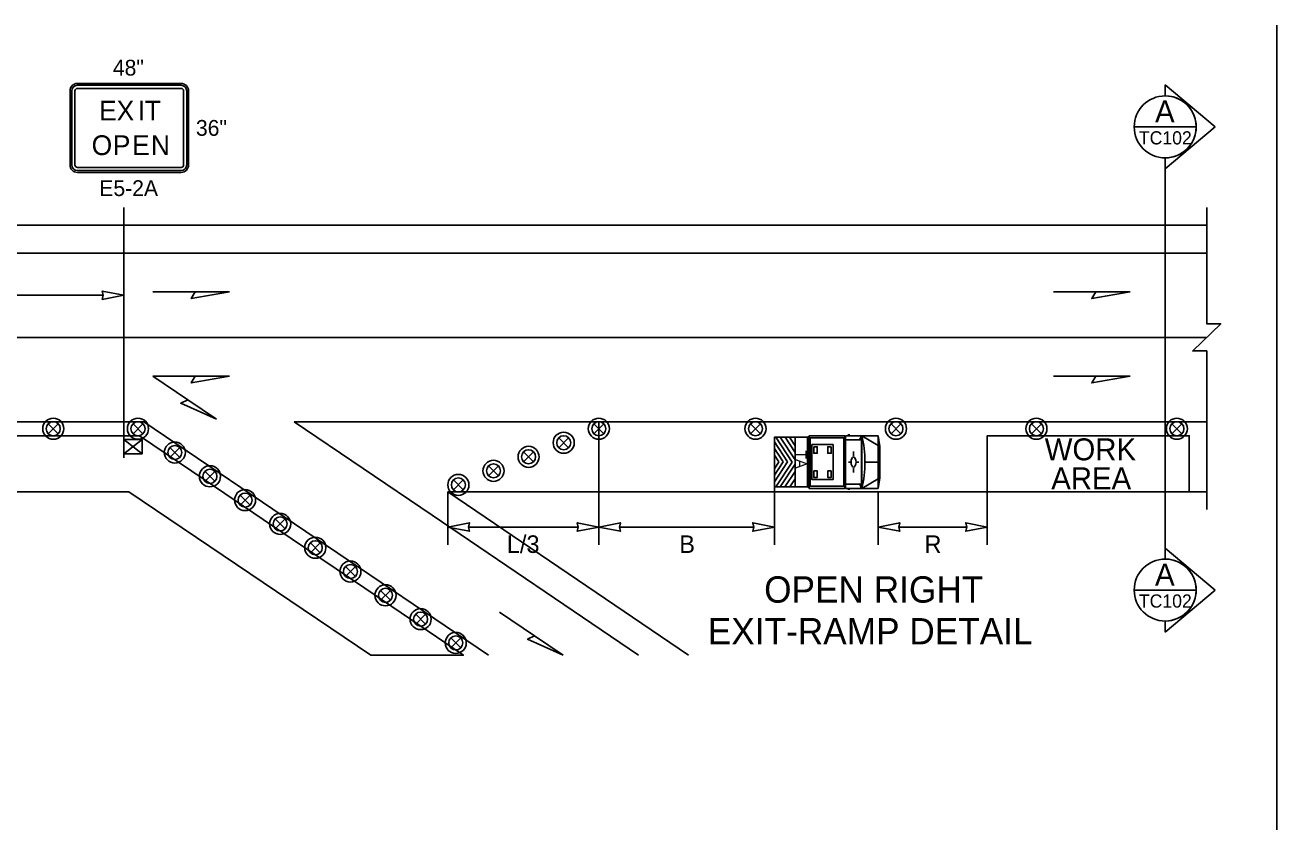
# Model space of a CAD drawing. Extents: x 99999.1 to 100055.7, y 99995 to 100013.2.
# Drawn here: x 100022.17 to 100027.88, y 100005.29 to 100008.92 of the extents above; entities that cross this region are included whole.
import ezdxf

# ---------------------------------------------------------------- set-up
doc = ezdxf.new("R2010")
doc.units = 0
for name, color, linetype in [('RD_MK_LineEdgeYellow', 7, 'Continuous'), ('RD_MK_LineLane', 7, 'Continuous'), ('SH_DE_DetailHeading2Text', 7, 'Continuous'), ('SH_TI_WZSectionCut', 7, 'Continuous'), ('TR_SN_ConstructionSigns', 7, 'Continuous'), ('TR_WZ_PortableSignMount5ftMinBlk-Org', 7, 'Continuous'), ('TR_WZ_TrafficSafetyDrum', 7, 'Continuous'), ('TR_WZ_TransportableAttenuator', 7, 'Continuous'), ('TR_WZ_WorkAreaLabel', 7, 'Continuous'), ('TR_WZ_WorkZoneDetails', 7, 'Continuous'), ('TR_WZ_WorkZoneTextCurrent', 7, 'Continuous')]:
    doc.layers.add(name, color=color, linetype=linetype)

msp = doc.modelspace()

# ---------------------------------------------------------------- linework, layer by layer
at = {"layer": 'RD_MK_LineEdgeYellow'}
for p, q in [((100020.32, 100007.8789), (100027.555, 100007.8789)), ((100020.32, 100007.1109), (100022.7119, 100007.1109)), ((100024.2815, 100006.047), (100022.7119, 100007.1109)), ((100024.0968, 100007.1109), (100027.555, 100007.1109)), ((100024.9659, 100006.047), (100024.0249, 100006.6849))]:
    msp.add_line(p, q, dxfattribs=at)
at = {"layer": 'RD_MK_LineLane'}
msp.add_lwpolyline([(100027.555, 100007.4949), (100020.32, 100007.4949)], dxfattribs=at)
at = {"layer": 'SH_TI_WZSectionCut'}
for p, q in [((100027.3657, 100008.5953), (100027.3657, 100008.6452)), ((100027.3657, 100008.6452), (100027.5938, 100008.454)), ((100027.5938, 100008.454), (100027.3657, 100008.2629)), ((100027.3657, 100008.2629), (100027.3657, 100008.3128)), ((100027.3657, 100008.2629), (100027.3657, 100006.5349)), ((100027.3657, 100006.5349), (100027.3657, 100006.485)), ((100027.5939, 100006.3438), (100027.3657, 100006.5349)), ((100027.3657, 100006.1526), (100027.5939, 100006.3438)), ((100027.3657, 100006.2025), (100027.3657, 100006.1526))]:
    msp.add_line(p, q, dxfattribs=at)
for points in [[(100027.2245, 100008.4541), (100027.5069, 100008.4541)], [(100027.2245, 100006.3438), (100027.5069, 100006.3438)]]:
    msp.add_lwpolyline(points, dxfattribs=at)
for centre in [(100027.3657, 100008.454), (100027.3657, 100006.3438)]:
    msp.add_circle(centre, 0.1412, dxfattribs=at)
for centre in [(100027.3657, 100008.454), (100027.3657, 100006.3438)]:
    msp.add_arc(centre, 0.1412, 269.9978, 90.0022, dxfattribs=at)
at = {"layer": 'TR_SN_ConstructionSigns'}
for p, q in [((100022.3752, 100008.6182), (100022.3752, 100008.2807)), ((100022.3837, 100008.6182), (100022.3837, 100008.2807)), ((100022.3977, 100008.2807), (100022.3977, 100008.6182)), ((100022.8815, 100008.6519), (100022.409, 100008.6519)), ((100022.8815, 100008.6435), (100022.409, 100008.6435)), ((100022.409, 100008.6294), (100022.8815, 100008.6294)), ((100022.8927, 100008.6182), (100022.8927, 100008.2807)), ((100022.9068, 100008.2807), (100022.9068, 100008.6182)), ((100022.9152, 100008.2807), (100022.9152, 100008.6182)), ((100022.8815, 100008.2694), (100022.409, 100008.2694)), ((100022.409, 100008.2553), (100022.8815, 100008.2553)), ((100022.409, 100008.2469), (100022.8815, 100008.2469))]:
    msp.add_line(p, q, dxfattribs=at)
for centre, radius, start, end in [((100022.409, 100008.6182), 0.0338, 90, 180), ((100022.409, 100008.6182), 0.0253, 90, 180), ((100022.409, 100008.6182), 0.0112, 90, 180), ((100022.8815, 100008.6182), 0.0338, 360, 90), ((100022.8815, 100008.6182), 0.0253, 360, 90), ((100022.8815, 100008.6182), 0.0112, 360, 90), ((100022.409, 100008.2807), 0.0338, 180, 270), ((100022.409, 100008.2807), 0.0253, 180, 270), ((100022.409, 100008.2807), 0.0112, 180, 270), ((100022.8815, 100008.2807), 0.0338, 270, 0), ((100022.8815, 100008.2807), 0.0253, 270, 0), ((100022.8815, 100008.2807), 0.0112, 270, 0)]:
    msp.add_arc(centre, radius, start, end, dxfattribs=at)
at = {"layer": 'TR_WZ_PortableSignMount5ftMinBlk-Org'}
for p, q in [((100022.6202, 100007.0469), (100022.6202, 100006.9469)), ((100022.7036, 100006.9644), (100022.6202, 100007.0294)), ((100022.7036, 100007.0294), (100022.6202, 100006.9644)), ((100022.6619, 100006.9969), (100022.6619, 100006.9969)), ((100022.6621, 100006.9968), (100022.6621, 100006.9968))]:
    msp.add_line(p, q, dxfattribs=at)
for points in [[(100022.7036, 100006.9644), (100022.7036, 100007.0294), (100022.6202, 100007.0294), (100022.6202, 100006.9644)], [(100022.6202, 100007.0294), (100022.7036, 100007.0294), (100022.7036, 100006.9644), (100022.6202, 100006.9644)]]:
    msp.add_lwpolyline(points, close=True, dxfattribs=at)
at = {"layer": 'TR_WZ_TrafficSafetyDrum'}
for p, q in [((100022.2763, 100007.1015), (100022.3215, 100007.0563)), ((100022.3215, 100007.1015), (100022.2763, 100007.0563)), ((100022.6622, 100007.1015), (100022.7075, 100007.0563)), ((100022.7075, 100007.1015), (100022.6622, 100007.0563)), ((100024.7622, 100007.1015), (100024.8074, 100007.0563)), ((100024.8074, 100007.1015), (100024.7622, 100007.0563)), ((100025.4763, 100007.1015), (100025.5215, 100007.0563)), ((100025.5215, 100007.1015), (100025.4763, 100007.0563)), ((100026.1163, 100007.1015), (100026.1615, 100007.0563)), ((100026.1615, 100007.1015), (100026.1163, 100007.0563)), ((100026.7563, 100007.1015), (100026.8015, 100007.0563)), ((100026.8015, 100007.1015), (100026.7563, 100007.0563)), ((100027.3963, 100007.1015), (100027.4415, 100007.0563)), ((100027.4415, 100007.1015), (100027.3963, 100007.0563)), ((100024.6022, 100007.0375), (100024.6474, 100006.9923)), ((100024.6474, 100007.0375), (100024.6022, 100006.9923)), ((100022.8303, 100006.9931), (100022.8755, 100006.9478)), ((100022.8755, 100006.9931), (100022.8303, 100006.9478)), ((100024.4422, 100006.9735), (100024.4874, 100006.9283)), ((100024.4874, 100006.9735), (100024.4422, 100006.9283)), ((100024.2822, 100006.9095), (100024.3274, 100006.8643)), ((100024.3274, 100006.9095), (100024.2822, 100006.8643)), ((100022.9903, 100006.8846), (100023.0355, 100006.8394)), ((100023.0355, 100006.8846), (100022.9903, 100006.8394)), ((100024.1221, 100006.8455), (100024.1674, 100006.8003)), ((100024.1674, 100006.8455), (100024.1221, 100006.8003)), ((100023.1503, 100006.7762), (100023.1955, 100006.7309)), ((100023.1955, 100006.7762), (100023.1503, 100006.7309)), ((100023.3103, 100006.6677), (100023.3555, 100006.6225)), ((100023.3555, 100006.6677), (100023.3103, 100006.6225)), ((100023.4703, 100006.5593), (100023.5155, 100006.514)), ((100023.5155, 100006.5593), (100023.4703, 100006.514)), ((100023.6303, 100006.4508), (100023.6755, 100006.4056)), ((100023.6755, 100006.4508), (100023.6303, 100006.4056)), ((100023.7903, 100006.3424), (100023.8355, 100006.2971)), ((100023.8355, 100006.3424), (100023.7903, 100006.2971)), ((100023.9503, 100006.2339), (100023.9955, 100006.1887)), ((100023.9955, 100006.2339), (100023.9503, 100006.1887)), ((100024.1103, 100006.1255), (100024.1555, 100006.0802)), ((100024.1555, 100006.1255), (100024.1103, 100006.0802))]:
    msp.add_line(p, q, dxfattribs=at)
for centre, radius in [((100022.2989, 100007.0789), 0.048), ((100022.2989, 100007.0789), 0.048), ((100022.6849, 100007.0789), 0.048), ((100022.6849, 100007.0789), 0.048), ((100024.7848, 100007.0789), 0.048), ((100024.7848, 100007.0789), 0.048), ((100025.4989, 100007.0789), 0.048), ((100025.4989, 100007.0789), 0.048), ((100026.1389, 100007.0789), 0.048), ((100026.1389, 100007.0789), 0.048), ((100026.7789, 100007.0789), 0.048), ((100026.7789, 100007.0789), 0.048), ((100027.4189, 100007.0789), 0.048), ((100027.4189, 100007.0789), 0.048), ((100022.2989, 100007.0789), 0.032), ((100022.6849, 100007.0789), 0.032), ((100024.7848, 100007.0789), 0.032), ((100025.4989, 100007.0789), 0.032), ((100026.1389, 100007.0789), 0.032), ((100026.7789, 100007.0789), 0.032), ((100027.4189, 100007.0789), 0.032), ((100022.8529, 100006.9705), 0.048), ((100022.8529, 100006.9705), 0.048), ((100024.6248, 100007.0149), 0.048), ((100024.6248, 100007.0149), 0.048), ((100024.6248, 100007.0149), 0.032), ((100022.8529, 100006.9705), 0.032), ((100024.4648, 100006.9509), 0.048), ((100024.4648, 100006.9509), 0.048), ((100024.4648, 100006.9509), 0.032), ((100023.0129, 100006.862), 0.048), ((100023.0129, 100006.862), 0.048), ((100023.0129, 100006.862), 0.032), ((100024.3048, 100006.8869), 0.048), ((100024.3048, 100006.8869), 0.048), ((100024.3048, 100006.8869), 0.032), ((100024.1448, 100006.8229), 0.048), ((100024.1448, 100006.8229), 0.048), ((100024.1448, 100006.8229), 0.032), ((100023.1729, 100006.7536), 0.048), ((100023.1729, 100006.7536), 0.048), ((100023.1729, 100006.7536), 0.032), ((100023.3329, 100006.6451), 0.048), ((100023.3329, 100006.6451), 0.048), ((100023.3329, 100006.6451), 0.032), ((100023.4929, 100006.5367), 0.048), ((100023.4929, 100006.5367), 0.048), ((100023.4929, 100006.5367), 0.032), ((100023.6529, 100006.4282), 0.048), ((100023.6529, 100006.4282), 0.048), ((100023.6529, 100006.4282), 0.032), ((100023.8129, 100006.3198), 0.048), ((100023.8129, 100006.3198), 0.048), ((100023.8129, 100006.3198), 0.032), ((100023.9729, 100006.2113), 0.048), ((100023.9729, 100006.2113), 0.048), ((100023.9729, 100006.2113), 0.032), ((100024.1329, 100006.1029), 0.048), ((100024.1329, 100006.1029), 0.048), ((100024.1329, 100006.1029), 0.032)]:
    msp.add_circle(centre, radius, dxfattribs=at)
at = {"layer": 'TR_WZ_TransportableAttenuator'}
for p, q in [((100025.5848, 100007.0184), (100025.6449, 100006.9278)), ((100025.5848, 100006.9892), (100025.5848, 100007.0184)), ((100025.6449, 100006.9278), (100025.5848, 100007.0184)), ((100025.5848, 100007.0184), (100025.5848, 100006.9892)), ((100025.6659, 100006.9271), (100025.591, 100007.0398)), ((100025.591, 100007.0398), (100025.6114, 100007.0398)), ((100025.591, 100007.0398), (100025.6659, 100006.9271)), ((100025.6114, 100007.0398), (100025.591, 100007.0398)), ((100025.6114, 100007.0398), (100025.6792, 100006.9371)), ((100025.6792, 100006.9371), (100025.6114, 100007.0398)), ((100025.6792, 100006.9703), (100025.6336, 100007.0398)), ((100025.6336, 100007.0398), (100025.6539, 100007.0398)), ((100025.6539, 100007.0398), (100025.6336, 100007.0398)), ((100025.6336, 100007.0398), (100025.6792, 100006.9703)), ((100025.6539, 100007.0398), (100025.6792, 100007.0016)), ((100025.6792, 100007.0016), (100025.6539, 100007.0398)), ((100025.6792, 100006.8145), (100025.6792, 100007.0398)), ((100025.7436, 100007.0398), (100025.6792, 100007.0398)), ((100025.7359, 100007.0357), (100025.7359, 100006.8182)), ((100025.7395, 100007.043), (100025.743, 100007.043)), ((100025.743, 100007.043), (100025.743, 100006.8108)), ((100025.7436, 100007.0469), (100025.9061, 100007.0469)), ((100025.7436, 100007.0469), (100025.7436, 100006.8069)), ((100025.7436, 100007.0394), (100025.7436, 100006.8145)), ((100025.7482, 100007.0374), (100025.7482, 100006.8165)), ((100025.7482, 100007.0374), (100025.9015, 100007.0374)), ((100025.9015, 100007.0374), (100025.9015, 100006.8165)), ((100025.9061, 100007.0469), (100025.9061, 100006.8069)), ((100025.9083, 100007.0469), (100025.9083, 100006.8069)), ((100026.0575, 100007.0469), (100025.9083, 100007.0469)), ((100025.9815, 100007.0283), (100025.9083, 100007.0283)), ((100025.9286, 100007.0503), (100025.9196, 100007.0503)), ((100025.9815, 100007.0469), (100025.972, 100007.0283)), ((100025.9815, 100007.0469), (100025.9815, 100006.8069)), ((100025.9829, 100007.0469), (100025.9829, 100006.8069)), ((100026.0575, 100007.003), (100025.9829, 100007.0469)), ((100026.0575, 100007.0469), (100026.0575, 100006.8069)), ((100026.0575, 100007.0469), (100026.0648, 100006.9985)), ((100025.6256, 100006.9281), (100025.5848, 100006.9892)), ((100025.5848, 100006.9892), (100025.6256, 100006.9281)), ((100025.5848, 100006.9583), (100025.6057, 100006.9273)), ((100025.5848, 100006.8959), (100025.5848, 100006.9583)), ((100025.6057, 100006.9273), (100025.5848, 100006.9583)), ((100025.5848, 100006.9583), (100025.5848, 100006.8959)), ((100025.6792, 100007.0016), (100025.6792, 100006.9703)), ((100025.6792, 100006.9703), (100025.6792, 100007.0016)), ((100025.9457, 100006.9745), (100025.9457, 100006.9551)), ((100026.0648, 100006.9985), (100026.0648, 100006.8554)), ((100025.5848, 100006.8667), (100025.6256, 100006.9281)), ((100025.6256, 100006.9281), (100025.5848, 100006.8667)), ((100025.6449, 100006.9278), (100025.5848, 100006.8373)), ((100025.5848, 100006.8373), (100025.6449, 100006.9278)), ((100025.6057, 100006.9273), (100025.5848, 100006.8959)), ((100025.5848, 100006.8959), (100025.6057, 100006.9273)), ((100025.591, 100006.8144), (100025.6659, 100006.9271)), ((100025.6659, 100006.9271), (100025.591, 100006.8144)), ((100025.6792, 100006.917), (100025.611, 100006.8144)), ((100025.611, 100006.8144), (100025.6792, 100006.917)), ((100025.6792, 100006.9371), (100025.6792, 100006.917)), ((100025.6792, 100006.917), (100025.6792, 100006.9371)), ((100025.7359, 100006.9438), (100025.743, 100006.9393)), ((100025.7359, 100006.91), (100025.743, 100006.9145)), ((100025.7378, 100006.9269), (100025.7411, 100006.9269)), ((100025.7395, 100006.9303), (100025.7395, 100006.9235)), ((100025.9219, 100006.9271), (100025.9318, 100006.927)), ((100025.9346, 100006.9265), (100025.9346, 100006.9265)), ((100025.9457, 100006.8794), (100025.9457, 100006.8988)), ((100025.9695, 100006.9271), (100025.9596, 100006.927)), ((100026.0575, 100006.9269), (100025.9975, 100006.9269)), ((100025.5848, 100006.8373), (100025.5848, 100006.8667)), ((100025.5848, 100006.8667), (100025.5848, 100006.8373)), ((100025.633, 100006.8144), (100025.6792, 100006.8838)), ((100025.6792, 100006.8838), (100025.633, 100006.8144)), ((100025.6792, 100006.8507), (100025.6546, 100006.8144)), ((100025.6546, 100006.8144), (100025.6792, 100006.8507)), ((100025.6792, 100006.8838), (100025.6792, 100006.8507)), ((100025.6792, 100006.8507), (100025.6792, 100006.8838)), ((100026.0575, 100006.8509), (100025.9829, 100006.8069)), ((100026.0575, 100006.8069), (100026.0648, 100006.8554)), ((100025.611, 100006.8144), (100025.591, 100006.8144)), ((100025.591, 100006.8144), (100025.611, 100006.8144)), ((100025.6546, 100006.8144), (100025.633, 100006.8144)), ((100025.633, 100006.8144), (100025.6546, 100006.8144)), ((100025.7436, 100006.8145), (100025.6792, 100006.8145)), ((100025.7395, 100006.8108), (100025.743, 100006.8108)), ((100025.7436, 100006.8069), (100025.9061, 100006.8069)), ((100025.7482, 100006.8165), (100025.9015, 100006.8165)), ((100025.9815, 100006.8255), (100025.9083, 100006.8255)), ((100026.0575, 100006.8069), (100025.9083, 100006.8069)), ((100025.9286, 100006.8036), (100025.9196, 100006.8036)), ((100025.9737, 100006.8255), (100025.9815, 100006.8069))]:
    msp.add_line(p, q, dxfattribs=at)
for points in [[(100025.6792, 100006.8144), (100025.5848, 100006.8144), (100025.5848, 100007.0398), (100025.6792, 100007.0398)], [(100025.7562, 100007.0069), (100025.8522, 100007.0069), (100025.8522, 100006.8469), (100025.7562, 100006.8469)], [(100025.7642, 100006.9969), (100025.7802, 100006.9969), (100025.7802, 100006.9669), (100025.7642, 100006.9669)], [(100025.8442, 100006.9969), (100025.8282, 100006.9969), (100025.8282, 100006.9669), (100025.8442, 100006.9669)], [(100025.7642, 100006.8869), (100025.7802, 100006.8869), (100025.7802, 100006.8569), (100025.7642, 100006.8569)], [(100025.8442, 100006.8869), (100025.8282, 100006.8869), (100025.8282, 100006.8569), (100025.8442, 100006.8569)]]:
    msp.add_lwpolyline(points, close=True, dxfattribs=at)
msp.add_lwpolyline([(100025.6792, 100007.0398), (100025.5848, 100007.0398), (100025.5848, 100006.8144), (100025.6792, 100006.8145)], dxfattribs=at)
for centre, major_axis, start_param, end_param in [((100025.7395, 100007.0357), (0, 0.00732), 6.283185, 7.853982), ((100025.8762, 100006.9269), (0, 0.2519), 4.215852, 5.209111), ((100025.7395, 100006.8182), (0, -0.00732), 4.712389, 6.283185)]:
    msp.add_ellipse(centre, major_axis=major_axis, ratio=0.481608, start_param=start_param, end_param=end_param, dxfattribs=at)
for centre, major_axis in [((100025.7395, 100006.9269), (0, -0.00338)), ((100025.9457, 100006.9269), (0, -0.0231))]:
    msp.add_ellipse(centre, major_axis=major_axis, ratio=0.481608, dxfattribs=at)
at = {"layer": 'TR_WZ_WorkZoneDetails'}
for p, q in [((100027.875, 100008.9181), (100027.875, 100001.5759)), ((100022.6202, 100007.0469), (100022.6202, 100008.0869)), ((100020.32, 100008.0069), (100027.555, 100008.0069)), ((100022.9452, 100007.7023), (100022.7523, 100007.7023)), ((100027.0492, 100007.7023), (100026.8563, 100007.7023)), ((100022.5265, 100007.6869), (100020.4137, 100007.6869)), ((100022.912, 100007.2101), (100022.7523, 100007.3183)), ((100022.9452, 100007.3183), (100022.7523, 100007.3183)), ((100027.0492, 100007.3183), (100026.8563, 100007.3183)), ((100024.0249, 100006.6849), (100023.3963, 100007.1109)), ((100023.3963, 100007.1109), (100024.0968, 100007.1109)), ((100024.7848, 100006.5495), (100024.7848, 100007.1109)), ((100020.32, 100006.7909), (100022.6438, 100006.7909)), ((100022.6438, 100006.7909), (100023.746, 100006.047)), ((100025.1937, 100006.047), (100024.0968, 100006.7909)), ((100024.0968, 100006.7909), (100027.555, 100006.7909)), ((100024.0968, 100006.7909), (100024.0968, 100006.5495)), ((100025.5848, 100006.5495), (100025.5848, 100006.8144)), ((100026.0575, 100006.7909), (100026.0575, 100006.5495)), ((100026.5552, 100006.7909), (100026.5552, 100006.5495)), ((100024.6911, 100006.6309), (100024.1905, 100006.6309)), ((100025.4911, 100006.6309), (100024.8785, 100006.6309)), ((100026.4615, 100006.6309), (100026.1512, 100006.6309)), ((100024.492, 100006.1352), (100024.3323, 100006.2435))]:
    msp.add_line(p, q, dxfattribs=at)
msp.add_lwpolyline([(100027.555, 100006.7109), (100027.555, 100007.433), (100027.491, 100007.433), (100027.619, 100007.5569), (100027.555, 100007.5569), (100027.555, 100008.0869)], dxfattribs=at)
for points in [[(100022.6202, 100007.6869), (100022.5219, 100007.7062), (100022.5265, 100007.6869), (100022.5219, 100007.6676)], [(100023.1024, 100007.7023), (100022.9274, 100007.6715), (100022.9452, 100007.7023)], [(100027.2065, 100007.7023), (100027.0314, 100007.6715), (100027.0492, 100007.7023)], [(100023.1024, 100007.3183), (100022.9274, 100007.2875), (100022.9452, 100007.3183)], [(100027.2065, 100007.3183), (100027.0314, 100007.2875), (100027.0492, 100007.3183)], [(100023.0421, 100007.1219), (100022.8799, 100007.1946), (100022.912, 100007.2101)], [(100020.4, 100006.7909), (100022.6438, 100006.7909), (100023.746, 100006.047), (100024.1675, 100006.047), (100023.7179, 100006.3517), (100023.3873, 100006.5758), (100022.9905, 100006.8448), (100022.6923, 100007.0469), (100020.4, 100007.0469)], [(100026.5552, 100006.7909), (100026.5552, 100007.0469), (100027.475, 100007.0469), (100027.475, 100006.7909)], [(100024.0968, 100006.6309), (100024.1951, 100006.6116), (100024.1905, 100006.6309), (100024.1951, 100006.6502)], [(100024.7848, 100006.6309), (100024.6865, 100006.6116), (100024.6911, 100006.6309), (100024.6865, 100006.6502)], [(100024.7848, 100006.6309), (100024.8831, 100006.6502), (100024.8785, 100006.6309), (100024.8831, 100006.6116)], [(100025.5848, 100006.6309), (100025.4865, 100006.6502), (100025.4911, 100006.6309), (100025.4865, 100006.6116)], [(100026.0575, 100006.6309), (100026.1558, 100006.6116), (100026.1512, 100006.6309), (100026.1558, 100006.6502)], [(100026.5552, 100006.6309), (100026.4569, 100006.6116), (100026.4615, 100006.6309), (100026.4569, 100006.6502)], [(100024.6221, 100006.047), (100024.4599, 100006.1197), (100024.492, 100006.1352)]]:
    msp.add_lwpolyline(points, close=True, dxfattribs=at)

# ---------------------------------------------------------------- texts
at = {"layer": 'SH_DE_DetailHeading2Text'}
for s, p in [('OPEN RIGHT', (100025.5382, 100006.2863)), ('EXIT-RAMP DETAIL', (100025.2814, 100006.0963))]:
    msp.add_text(s, height=0.12, rotation=360, dxfattribs=at).set_placement(p)
at = {"layer": 'SH_TI_WZSectionCut'}
for s, height, rotation, p in [('A', 0.1, 0.01, (100027.3195, 100008.4747)), ('TC102', 0.06, 360, (100027.2459, 100008.3741)), ('A', 0.1, 0.01, (100027.3195, 100006.3644)), ('TC102', 0.06, 360, (100027.2459, 100006.2638))]:
    msp.add_text(s, height=height, rotation=rotation, dxfattribs=at).set_placement(p)
at = {"layer": 'TR_SN_ConstructionSigns'}
for s, height, p in [('48"', 0.072, (100022.5705, 100008.6879)), ('E', 0.09, (100022.5075, 100008.4832)), ('X', 0.09, (100022.5876, 100008.4832)), ('I', 0.09, (100022.6839, 100008.4832)), ('T', 0.09, (100022.7154, 100008.4832)), ('36"', 0.072, (100022.949, 100008.4134)), ('O', 0.09, (100022.4738, 100008.3257)), ('P', 0.09, (100022.5701, 100008.3257)), ('E', 0.09, (100022.6583, 100008.3257)), ('N', 0.09, (100022.7438, 100008.3257)), ('E5-2A', 0.072, (100022.5087, 100008.1389))]:
    msp.add_text(s, height=height, rotation=360, dxfattribs=at).set_placement(p)
at = {"layer": 'TR_WZ_TransportableAttenuator'}
msp.add_text('TA', height=0.048, rotation=270, dxfattribs=at).set_placement((100025.6836, 100006.9796))
at = {"layer": 'TR_WZ_WorkAreaLabel'}
for s, p in [('WORK', (100026.8169, 100006.9349)), ('AREA', (100026.8465, 100006.8029))]:
    msp.add_text(s, height=0.1, dxfattribs=at).set_placement(p)
at = {"layer": 'TR_WZ_WorkZoneTextCurrent'}
for s, p in [('L/3', (100024.3659, 100006.5129)), ('B', (100025.1516, 100006.5129)), ('R', (100026.2688, 100006.5129))]:
    msp.add_text(s, height=0.08, dxfattribs=at).set_placement(p)

doc.saveas('drawing.dxf')
